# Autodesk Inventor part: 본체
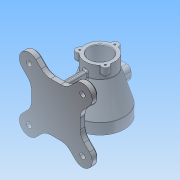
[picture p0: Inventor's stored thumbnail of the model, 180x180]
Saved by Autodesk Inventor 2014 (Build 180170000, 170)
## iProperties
Created: 2018-03
Part Number: 본체
Material: 알루미늄 6061
Document SubType Name: Modeling
Designer: net
Density: 2.71 g/cm^3
Appearance: 알루미늄 - 평지
Mass: 1014.31 g
Surface Area: 854.69 cm^2
Volume: 374.284 cm^3
Author: net
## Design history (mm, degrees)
sketch "스케치1"
  geometry: C1 r 45 at (0, 0); 1 further point
  constraints: 1 centre point, 1 coincident
  dimensions: "d0" = 90 diameter of C1
extrude "돌출1" new body sketch "스케치1" distance "d1" = 20; taper "d2" = 0 deg
node "작업 평면2"
sketch "스케치2"
  geometry: C1 r 27.5 at (0, 0); 1 further point
  constraints: 1 centre point, 1 coincident
  dimensions: "d4" = 55 diameter of C1
extrude "돌출2" join sketch "스케치2" distance "d5" = 23; taper "d6" = 0 deg
sketch "스케치3"
  geometry: L1 (-27.5, 77)-(27.5, 77) reference; L2 (-27.5, 100)-(27.5, 100) reference; L3 (45, 20)-(-45, 20) reference; L4 (-45, 0)-(45, 0) reference; L5 (27.5, 77)-(45, 20); L6 (-27.5, 77)-(-45, 20); L7 (0, 77)-(0, 20); L8 (27.5, 77)-(0, 77); L9 (45, 20)-(0, 20); L10 (27.5, 100)-(27.5, 77) reference; L11 (45, 0)-(45, 20) reference; 1 further point
  constraints: 10 end point, 2 collinear, 2 midpoint
revolve "회전1" sketch "스케치3" stored, may be unused: angle "d7" = 90 deg
sketch "스케치4"
  geometry: C1 r 27.5 at (0, 0) reference; C2 r 20 at (0, 0)
  constraints: 1 centre point, 1 coincident
  dimensions: "d8" = 40 diameter of C2
extrude "돌출3" cut sketch "스케치4" distance "d9" = 30; taper "d10" = 0 deg
sketch "스케치5"
  geometry: C1 r 20 at (0, 0) reference; C2 r 26 at (0, 0)
  constraints: 1 centre point, 1 coincident
  dimensions: "d11" = 52 diameter of C2
extrude "돌출4" cut sketch "스케치5" distance "d12" = 47; taper "d13" = 0 deg
sketch "스케치6"
  geometry: C1 r 45 at (0, 0) reference; C2 r 35 at (0, 0)
  constraints: 1 centre point, 1 coincident
  dimensions: "d14" = 70 diameter of C2
extrude "돌출5" cut sketch "스케치6" distance "d15" = 23; taper "d16" = 0 deg
sketch "스케치7"
  geometry: 1 further point
node "작업 평면3"
fillet "모깎기1" dims "d18" = 3
sketch "스케치8"
  geometry: C1 r 20 at (0, 0) reference; C2 r 7 at (0, 27.5); C3 r 7 at (-23.816, -13.75); C4 r 7 at (23.816, -13.75); 1 further point
  constraints: 3 centre point, 1 vertical alignment, 8 other
  dimensions: "d19" = 14 diameter of C2; "d22" = 360 deg dimension on C1.centre C2.centre (derived)
extrude "돌출6" join sketch "스케치8" distance "d24" = 15; taper "d25" = 0 deg
fillet "모깎기2" dims "d26" = 3
fillet "모깎기3" dims "d27" = 1
sketch "스케치9"
  geometry: A1 r 7 centre (0, 27.5) between (6.999, 27.373) and (-6.999, 27.373) reference; A2 r 7 centre (-23.816, -13.75) between (-27.205, -7.625) and (-20.206, -19.748) reference; A3 r 7 centre (23.816, -13.75) between (20.206, -19.748) and (27.205, -7.625) reference
hole "구멍1" sketch "스케치9" at (-23.816, -13.75), (0, 27.5), (23.816, -13.75) diameter "d28" = 3.242; stored, may be unused: countersink angle "d32" = 90 deg, drill point angle "d34" = 118 deg; dims "d29" = 9, "d30" = 4, "d31" = 2, "d33" = 11
sketch "스케치10"
  geometry: L1 (0, 0)-(0, 40); L2 (0, 0)-(-34.641, 20); L3 (0, 0)-(-34.641, -20); L4 (0, 0)-(0, -40); L5 (0, 0)-(34.641, -20); L6 (0, 0)-(34.641, 20); C1 r 35 at (0, 0) reference; C2 r 45 at (0, 0) reference
  constraints: 12 end point, 1 vertical, 19 other
  dimensions: "d35" = 40 distance of L1.start L1.end; "d38" = 360 deg dimension on C1.centre L1.end (derived)
hole "구멍2" sketch "스케치10" at (0, 40), (-34.641, 20), (-34.641, -20), (0, -40), (34.641, 20), (34.641, -20) diameter "d40" = 3.242; stored, may be unused: countersink angle "d44" = 90 deg, drill point angle "d46" = 118 deg; dims "d41" = 9, "d42" = 4, "d43" = 2, "d45" = 11
node "작업 평면4"
sketch "스케치14"
  geometry: L1 (-44.988, 69.554)-(-62.214, 86.78) reference; L2 (-44.988, 50.01)-(-44.988, 69.554) reference; L3 (-44.988, 69.554)-(-44.988, 30.466) reference; L4 (-44.988, 30.466)-(-62.214, 13.241) reference; L5 (0.012, 5.01)-(-19.532, 5.01) reference; L6 (-36.758, -12.215)-(-19.532, 5.01) reference; L7 (0.012, 5.01)-(19.556, 5.01) reference; L8 (36.781, -12.215)-(19.556, 5.01) reference; L9 (45.012, 30.466)-(62.237, 13.241) reference; L10 (45.012, 50.01)-(45.012, 30.466) reference; L11 (45.012, 50.01)-(45.012, 69.554) reference; L12 (45.012, 69.554)-(62.237, 86.78) reference; L13 (36.781, 112.236)-(19.556, 95.01) reference; L14 (0.012, 95.01)-(19.556, 95.01) reference; L15 (0.012, 95.01)-(-19.532, 95.01) reference; L16 (-36.758, 112.236)-(-19.532, 95.01) reference; A1 r 18 centre (-49.486, 99.508) between (-62.214, 86.78) and (-36.758, 112.236) reference; A2 r 18 centre (-49.486, 0.513) between (-62.214, 13.241) and (-36.758, -12.215) reference; A3 r 18 centre (49.509, 0.513) between (36.781, -12.215) and (62.237, 13.241) reference; A4 r 18 centre (49.509, 99.508) between (62.237, 86.78) and (36.781, 112.236) reference; 1 further point
extrude "돌출7" join sketch "스케치14" distance "d87" = 12; taper "d88" = 0 deg
sketch "스케치15"
  geometry: L1 (-62.237, -13.241)-(-45.012, -30.466) reference; L2 (-45.012, -30.466)-(-45.012, -69.554) reference; L3 (-45.012, -69.554)-(-62.237, -86.78) reference; L4 (-36.781, -112.236)-(-19.556, -95.01) reference; L5 (-19.556, -95.01)-(19.532, -95.01) reference; L6 (19.532, -95.01)-(36.758, -112.236) reference; L7 (62.214, -86.78)-(44.988, -69.554) reference; L8 (44.988, -69.554)-(44.988, -30.466) reference; L9 (44.988, -30.466)-(62.214, -13.241) reference; L10 (36.758, 12.215)-(19.532, -5.01) reference; L11 (19.532, -5.01)-(-19.556, -5.01) reference; L12 (-19.556, -5.01)-(-36.781, 12.215) reference; A1 r 18 centre (-49.509, -0.513) between (-36.781, 12.215) and (-62.237, -13.241) reference; A2 r 18 centre (-49.509, -99.508) between (-62.237, -86.78) and (-36.781, -112.236) reference; A3 r 18 centre (49.486, -99.508) between (36.758, -112.236) and (62.214, -86.78) reference; A4 r 18 centre (49.486, -0.513) between (62.214, -13.241) and (36.758, 12.215) reference; 1 further point
sketch "스케치16"
  geometry: L1 (-45.012, -30.466)-(-45.012, -69.554) reference; L2 (19.532, -5.01)-(-19.556, -5.01) reference; L3 (-45.012, -50.01)-(-0.012, -50.01); L4 (-0.012, -50.01)-(-0.012, -13.01); L5 (-0.012, -50.01)-(-0.012, -87.01); L6 (-0.012, -13.01)-(-4.012, -13.01); L7 (-4.012, -13.01)-(-4.012, -87.01); L8 (-4.012, -87.01)-(-0.012, -87.01); L9 (-0.012, -13.01)-(3.988, -13.01); L10 (3.988, -13.01)-(3.988, -87.01); L11 (3.988, -87.01)-(-0.012, -87.01); 1 further point
  constraints: 18 end point, 4 parallel, 3 perpendicular, 1 collinear, 1 midpoint
  dimensions: "d89" = 45 distance of L3.start L3.end; "d90" = 37 distance of L3.end L4.end; "d91" = 37 distance of L3.end L5.end; "d92" = 4 distance of L4.end L6.end; "d93" = 4 distance of L4.end L9.end
extrude "돌출8" join sketch "스케치16" stored distance "d94" = 12; taper "d95" = 0 deg
sketch "스케치17"
  geometry: 1 further point
node "작업 평면5"
sketch "스케치18"
  geometry: L1 (-4.012, -70)-(-4.012, -27.206) reference; L2 (3.988, -70)-(-4.012, -70) reference; L3 (3.988, -70)-(3.988, -27.209) reference; L4 (19.532, -70)-(-19.556, -70) reference; L5 (-0.012, -70)-(-24.012, -70); L6 (-24.012, -70)-(-19.879, -22.769); L7 (-24.012, -70)-(23.4, -70); L8 (-19.879, -22.769)-(-4.012, -30.433); L9 (-4.012, -70)-(-4.012, -30.433); L10 (-4.012, -70)-(-24.012, -70); A1 r 27.5 centre (0, 0) between (-4.012, -27.206) and (3.988, -27.209) reference; 1 further point
  constraints: 12 end point, 2 point on line, 1 collinear, 1 equal length, 1 horizontal, 1 midpoint, 1 perpendicular
  dimensions: "d97" = 24 distance of L5.start L5.end; "d98" = 85 deg angle of L7 L6
extrude "돌출9" join sketch "스케치18" stored distance "d99" = 8; taper "d100" = 0 deg
fillet "모깎기4" dims "d101" = 25
chamfer "모따기1" distance "d102" = 3; stored, may be unused: second distance "d103" = 2, angle "d104" = 45 deg
sketch "스케치19"
  geometry: C1 r 5 at (49.486, -99.508); C2 r 5 at (49.486, -0.513); C3 r 5 at (-49.509, -0.513); C4 r 5 at (-49.509, -99.508); A1 r 15 centre (49.486, -0.513) between (60.092, -11.119) and (38.879, 10.094) reference; A2 r 15 centre (-49.509, -0.513) between (-38.903, 10.094) and (-60.116, -11.119) reference; A3 r 15 centre (-49.509, -99.508) between (-60.116, -88.901) and (-38.903, -110.114) reference; A4 r 15 centre (49.486, -99.508) between (38.879, -110.114) and (60.092, -88.901) reference; 1 further point
  constraints: 4 centre point, 4 coincident
  dimensions: "d105" = 10 diameter of C1; "d106" = 10 diameter of C2; "d107" = 10 diameter of C3; "d108" = 10 diameter of C4
extrude "돌출10" cut sketch "스케치19" stored distance "d109" = 8; taper "d110" = 0 deg
fillet "모깎기5" dims "d111" = 3
fillet "모깎기6" dims "d112" = 3
fillet "모깎기7" dims "d113" = 3
fillet "모깎기8" dims "d114" = 3
sketch "스케치20"
  geometry: L1 (-33.02, 11)-(-33.02, 0) reference; L2 (-45, 0)-(45, 0) reference; L3 (0, 0)-(0, 50); L4 (12.5, 37.5)-(-12.5, 37.5); L5 (-12.5, 37.5)-(-12.5, 62.5); L6 (-12.5, 62.5)-(12.5, 62.5); L7 (12.5, 62.5)-(12.5, 37.5); L8 (12.5, 37.5)-(-12.5, 62.5); L9 (-12.5, 37.5)-(12.5, 62.5)
  constraints: 14 end point, 2 midpoint, 2 parallel, 2 perpendicular, 1 horizontal
  dimensions: "d115" = 50 distance of L3.start L3.end; "d116" = 25 distance of L5.end L6.end; "d117" = 25 distance of L4.end L5.end
extrude "돌출11" join sketch "스케치20" stored distance "d118" = 8; taper "d119" = 0 deg
sketch "스케치21"
  geometry: L1 (-7.5, -57.5)-(7.5, -57.5); L2 (7.5, -57.5)-(7.5, -42.5); L3 (7.5, -42.5)-(-7.5, -42.5); L4 (-7.5, -42.5)-(-7.5, -57.5); L5 (-7.5, -57.5)-(7.5, -42.5); L6 (7.5, -57.5)-(-7.5, -42.5); 2 further points
  constraints: 12 end point, 2 midpoint, 2 parallel, 1 horizontal, 1 perpendicular
  dimensions: "d120" = 15 distance of L3.end L2.end; "d121" = 15 distance of L2.end L1.end
extrude "돌출12" cut sketch "스케치21" distance "d122" = 40; taper "d123" = 0 deg
fillet "모깎기9" dims "d124" = 8
fillet "모깎기10" dims "d125" = 1
fillet "모깎기11" dims "d126" = 3
chamfer "모따기2" distance "d127" = 1; stored, may be unused: second distance "d128" = 2, angle "d129" = 45 deg
chamfer "모따기3" distance "d130" = 1; stored, may be unused: second distance "d131" = 2, angle "d132" = 45 deg
sketch "스케치22"
  geometry: 1 further point
fillet "모깎기12" dims "d133" = 3
sketch "스케치23"
  geometry: 1 further point
node "솔리드1"
mirror "대칭1"
node "투영된 루프2"
node "투영된 루프6"
other parameters: "d17" = 45, "d47" = -82
